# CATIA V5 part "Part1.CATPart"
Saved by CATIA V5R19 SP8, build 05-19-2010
Part number: Part1
Bounding box of the stored display mesh (mm): x -330.161 to 330.161, y 145 to 1080, z -87.192 to 130
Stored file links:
  G:\EU_thinkMotion\CFAO_2010\MMS_groupe2\MMS_groupe2\A reprendre\splanchenault\Planchenault\Part1.CATPart
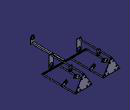
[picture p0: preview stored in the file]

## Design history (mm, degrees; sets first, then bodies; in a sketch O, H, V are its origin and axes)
Body1 (main body)
  Plane1: stored without definition
  DatumPoint1 to DatumPoint9
  Sketch1 on Plane1, origin (0, 1030, 0), H (-1, 0, 0), V (0, 0, 1)
    circle A1 centre (178.3494, 67.5) radius 7.5
    point P1 (178.3494, 67.5)
    point P2 (221.6506, 67.5)
    circle A2 centre (221.6506, 67.5) radius 7.5
    point P3 (200, 105)
    circle A3 centre (200, 105) radius 7.5
    reference projected point E1 (200, 105) from vertex of DatumPoint1
    reference projected point E2 (221.6506, 67.5) from vertex of DatumPoint2
    reference projected point E3 (178.3494, 67.5) from vertex of DatumPoint3
    point P4 (290.9327, -52.5)
    circle A4 centre (290.9327, -52.5) radius 7.5
    point P5 (247.6314, -52.5)
    circle A5 centre (247.6314, -52.5) radius 7.5
    point P6 (269.282, -15)
    circle A6 centre (269.282, -15) radius 7.5
    point P7 (130.718, -15)
    circle A7 centre (130.718, -15) radius 7.5
    point P8 (109.0673, -52.5)
    circle A8 centre (109.0673, -52.5) radius 7.5
    point P9 (152.3686, -52.5)
    circle A9 centre (152.3686, -52.5) radius 7.5
    reference projected point E4 (290.9327, -52.5) from vertex of DatumPoint4
    reference projected point E5 (269.282, -15) from vertex of DatumPoint5
    reference projected point E6 (247.6314, -52.5) from vertex of DatumPoint6
    reference projected point E7 (152.3686, -52.5) from vertex of DatumPoint7
    reference projected point E8 (130.718, -15) from vertex of DatumPoint8
    reference projected point E9 (109.0673, -52.5) from vertex of DatumPoint9
    line L1 (319.9832, -69.9742) -> (200, 130)
    line L2 (200, 130) -> (80, -69.9742)
    line L3 (80, -69.9742) -> (319.9832, -69.9742)
    radius A1 = 7.5 {= Sketch1.radius(A3)}
    radius A2 = 7.5 {= Sketch1.radius(A3)}
    radius A3 = 7.5
    distance P3 E1 = 0
    distance P2 E2 = 0
    distance P1 E3 = 0
    distance P4 E4 = 0
    distance P6 E5 = 0
    distance P5 E6 = 0
    distance P9 E7 = 0
    distance P7 E8 = 0
    distance P8 E9 = 0
    radius A8 = 7.5 {= Sketch1.radius(A3)}
    radius A7 = 7.5 {= Sketch1.radius(A3)}
    radius A9 = 7.5 {= Sketch1.radius(A3)}
    radius A5 = 7.5 {= Sketch1.radius(A3)}
    radius A6 = 7.5 {= Sketch1.radius(A3)}
    radius A4 = 7.5 {= Sketch1.radius(A3)}
    horizontal: L3 H
  Pad1: profile Sketch1, direction (0, 1, 0), length 50, opposite side length -45
  Plane2: stored without definition
  Sketch2 on start face of Pad1, origin (0, 1075, 0), H (1, 0, 0), V (0, 0, 1)
    line L1 (-200, 130) -> (-194, 120)
    line L2 (-80, -70) -> (-92, -70)
    line L3 (-320, -70) -> (-314, -60)
    line L4 (-206, 120) -> (-194, 120)
    point P4 (-206, 120)
    line L5 (-314, -60) -> (-308, -70)
    point P7 (-308, -70)
    line L6 (-86, -60) -> (-92, -70)
    point P8 (-86, -60)
    line L7 (-86, -60) -> (-80, -70)
    line L8 (-206, 120) -> (-200, 130)
    line L9 (-308, -70) -> (-320, -70)
    horizontal: L2 H, L4 H, L9 H
    coincidence: P4 L3, P7 L2, P8 L1, L1 L7, L3 L8, L2 L9
    parallelism: L5 L1, L6 L3
  Pad2: profile Sketch2, direction (0, -1, 0), length 465
  DatumPoint10 to DatumPoint14
  Plane3: stored without definition
  Sketch3 on Plane2, origin (0, 1030, 0), H (-1, 0, 0), V (0, 0, 1)
    circle A1 centre (269.282, -40) radius 15
    point P1 (269.282, -40)
    point P2 (130.718, -40)
    circle A2 centre (130.718, -40) radius 15
    point P3 (200, 80)
    circle A3 centre (200, 80) radius 15
    reference projected point E1 (200, 80) from vertex of DatumPoint10
    reference projected point E2 (269.282, -40) from vertex of DatumPoint11
    reference projected point E3 (130.718, -40) from vertex of DatumPoint12
    line L1 (180, 60) -> (180, 130)
    line L2 (180, 130) -> (220, 130)
    line L3 (220, 130) -> (220, 60)
    line L4 (220, 60) -> (180, 60)
    line L5 (262.2439, -12.6054) -> (241.8874, -47.0382)
    line L6 (241.8874, -47.0382) -> (309.805, -87.1906)
    point P10 (309.805, -87.1906)
    line L7 (309.805, -87.1906) -> (330.1614, -52.7578)
    line L8 (330.1614, -52.7578) -> (262.2439, -12.6054)
    line L9 (158.1115, -47.0422) -> (137.7601, -12.6064)
    line L10 (137.7601, -12.6064) -> (69.8243, -52.7563)
    line L11 (69.8243, -52.7563) -> (90.1757, -87.192)
    point P15 (90.1757, -87.192)
    line L12 (90.1757, -87.192) -> (158.1115, -47.0422)
    reference projected point E4 (200, 80) from vertex of DatumPoint13
    reference projected point E5 (200, 130) from vertex [face of Pad1 from Sketch1.L2 | end face of Pad1 | face of Pad1 from Sketch1.L1]
    reference projected point E6 (200, 80) from vertex of DatumPoint14
    reference projected point E7 (319.9832, -69.9742) from vertex [face of Pad1 from Sketch1.L3 | end face of Pad1 | face of Pad1 from Sketch1.L1]
    reference projected point E8 (319.9832, -69.9742) from vertex [face of Pad1 from Sketch1.L3 | end face of Pad1 | face of Pad1 from Sketch1.L1]
    reference projected point E9 (80, -69.9742) from vertex [face of Pad1 from Sketch1.L3 | end face of Pad1 | face of Pad1 from Sketch1.L2]
    reference projected point E10 (80, -69.9742) from vertex [face of Pad1 from Sketch1.L3 | end face of Pad1 | face of Pad1 from Sketch1.L2]
    radius A1 = 15
    radius A3 = 15
    radius A2 = 15
    distance P3 E1 = 0
    distance P1 E2 = 0
    distance P2 E3 = 0
    length L7 = 40 {= Sketch3.distance(L1 L3)}
    length L4 = 40 {= Sketch3.distance(L1 L3)}
    distance L1 L3 = 40
    distance L1 E4 = 20 {= Sketch3.distance(L1 L3) /2}
    distance L2 E5 = 0
    distance L4 E6 = 20
    distance P10 E7 = 20 {= Sketch3.length(L7) /2}
    angle L7 L5 = 0
    distance L8 P1 = 20 {= Sketch3.length(L7) /2}
    distance L7 E8 = 0
    distance L5 P1 = 20
    distance P15 E9 = 20 {= Sketch3.distance(L10 L12) /2}
    distance L10 P2 = 20 {= Sketch3.distance(L10 L12) /2}
    distance L10 L12 = 40 {= Sketch3.distance(L1 L3)}
    distance L11 E10 = 0
    angle L10 L11 = 90
    distance L9 P2 = 20
    horizontal: L2 H, L4 H
    perpendicularity: L6 L5
    parallelism: L8 L6, L11 L9
  Pad3: profile Sketch3, direction (0, -1, 0), length 140, opposite side length -135
  Sketch4, origin (0, 300, 0), H (-1, 0, 0), V (0, 0, 1), geometry linked from another document
  Sketch5, origin (0, 300, 0), H (-1, 0, 0), V (0, 0, 1), geometry linked from another document
  Sketch6 on Plane3, origin (0, 750, 0), H (-1, 0, 0), V (0, 0, 1)
    line L1 (170, 130) -> (170, -30)
    line L2 (170, -30) -> (230, -30)
    line L3 (230, -30) -> (230, 130)
    line L4 (230, 130) -> (170, 130)
    reference projected line E1 (214, 130) -> (186, 130) from edge [face of Pad3 | start face of Pad3]
    reference projected point E2 (200, 0) from Sketch4
    reference projected point E3 (200, 0) from Sketch5
    circle A1 centre (200, 0) radius 25
    point P5 (200, 0)
    distance L4 E1 = 0
    distance L2 E2 = 30
    distance L1 L3 = 60
    distance L3 E3 = 30
    radius A1 = 25
    vertical: L1 V, L3 V
    horizontal: L2 H, L4 H
    coincidence: P5 H
  Pad4: profile Sketch6, direction (0, -1, 0), length 140, opposite side length -135
  Mirror1: of the body so far, about yz-plane
  Sketch7 on face of Pad4, origin (0, 610, 0), H (1, 0, 0), V (0, 0, 1)
    line L1 (-320, -70) -> (320, -70)
    line L2 (320, -70) -> (320, -60)
    line L3 (-320, -70) -> (-320, -60)
    line L4 (-320, -60) -> (320, -60)
    horizontal: L1 H, L4 H
    vertical: L2 V, L3 V
  Pad5: profile Sketch7, direction (0, -1, 0), length 10
  Sketch8 on end face of Pad5, origin (0, 600, 0), H (1, 0, 0), V (0, 0, 1)
    line L1 (-10, -70) -> (10, -70)
    line L2 (10, -70) -> (10, -50)
    line L3 (10, -50) -> (-10, -50)
    line L4 (-10, -50) -> (-10, -70)
    horizontal: L1 H, L3 H
    vertical: L2 V, L4 V
  Pad6: profile Sketch8, direction (0, -1, 0), length 450
  Fillet1: radius 5, on edge [face of Pad5 from Sketch7.L4 | start face of Pad6]
  Sketch9 on end face of Pad6, origin (0, 150, 0), H (1, 0, 0), V (0, 0, 1)
    line L1 (-30, -70) -> (30, -70)
    line L2 (30, -70) -> (30, 5.3187)
    line L3 (5, 30.3187) -> (-5, 30.3187)
    line L4 (-30, 5.3187) -> (-30, -70)
    arc A1 centre (-5, 5.3187) radius 25 from (-5, 30.3187) to (-30, 5.3187) ccw
    arc A2 centre (5, 5.3187) radius 25 from (30, 5.3187) to (5, 30.3187) ccw
    circle A3 centre (0, 0) radius 20
    point P9 (0, 20)
    radius A1 = 25
    radius A2 = 25
    distance L4 V = 30
    distance L2 V = 30
    radius A3 = 20
    horizontal: L1 H, L3 H
    vertical: L2 V, L4 V
    tangency: A1 L3, A1 L4, A2 L2, A2 L3
    coincidence: A3 P9, P9 V
  Pad7: profile Sketch9, direction (0, -1, 0), length 5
